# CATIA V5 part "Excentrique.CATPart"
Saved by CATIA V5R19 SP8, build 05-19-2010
Part number: Excentrique
Revision: ANY
Definition: UNKNOWN
Nomenclature: 15
Source: Unknown
Bounding box of the stored display mesh (mm): x -11.99 to 11.99, y -12 to 12, z 0 to 8
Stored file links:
  D:\Documents\1_Travail\2- 2I2D\1 - Cours et TD\2- TD\3-TD Assemblage\Pompe AirMan\Excentrique.CATPart
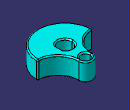
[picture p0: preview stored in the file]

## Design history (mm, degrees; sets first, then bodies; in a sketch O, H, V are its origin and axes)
Body1 "Chanfrein1" (main body)
  Solid1: solid without history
